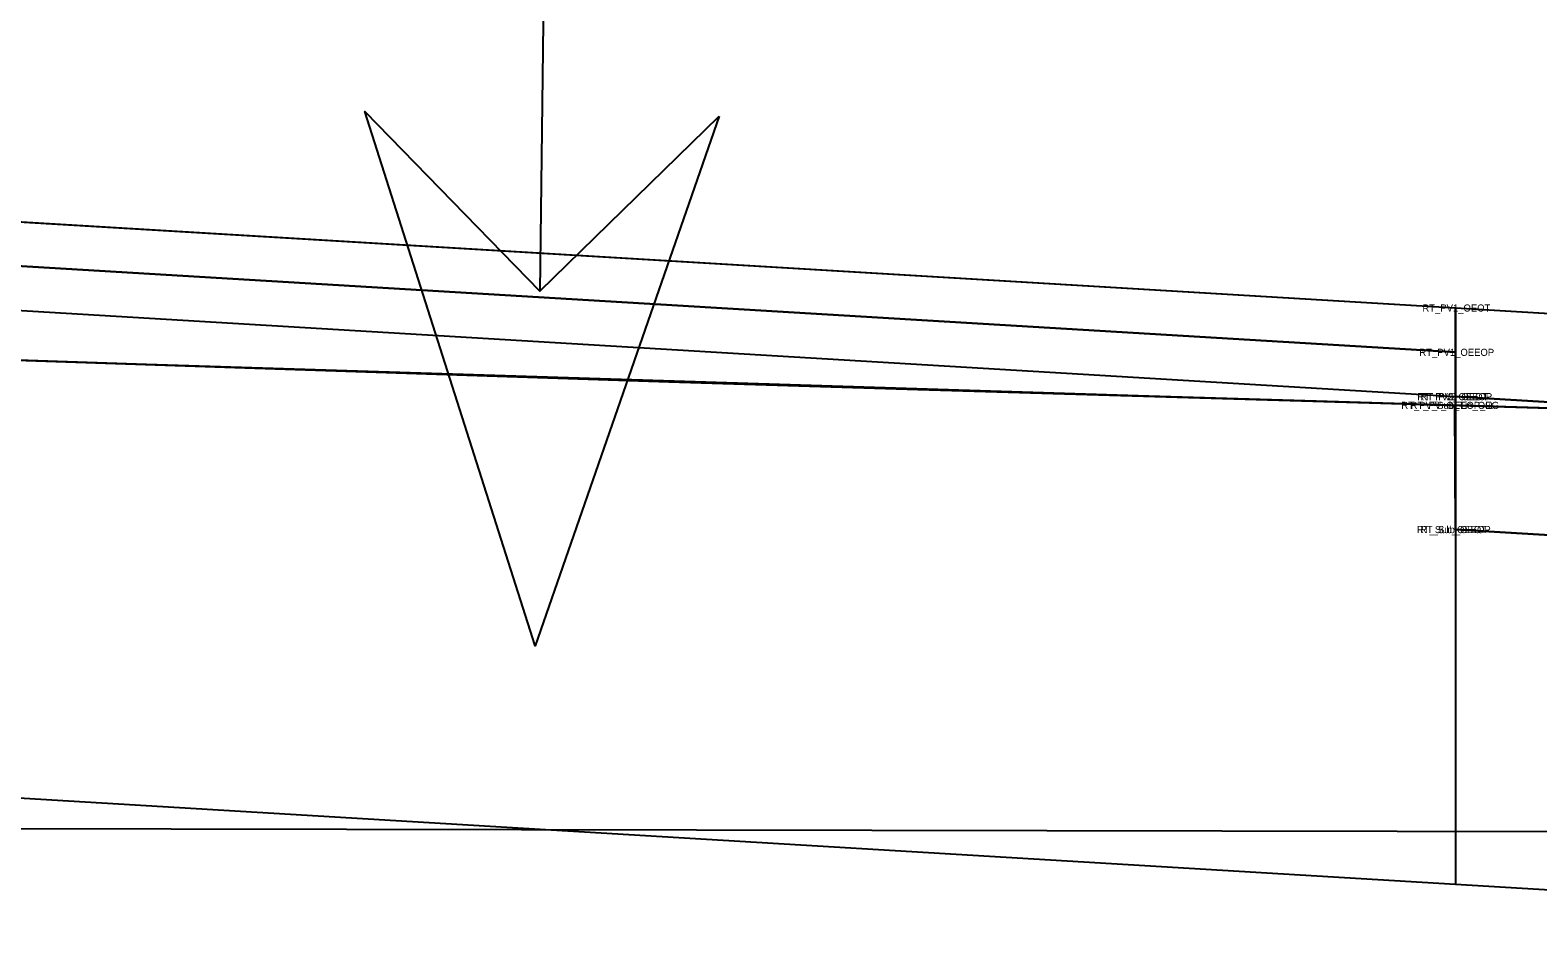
# Model space of a CAD drawing. Extents: x -516 to 303, y -10 to 5017.
# Drawn here: x 157.507 to 161.762, y 3502.323 to 3504.892 of the extents above; entities that cross this region are included whole.
import ezdxf

# ---------------------------------------------------------------- set-up
doc = ezdxf.new("R2010")
doc.units = 0
for name, color, linetype in [('Exist CMT Pavement', 7, 'Continuous'), ('Exist XS Ground Line', 7, 'Continuous'), ('Misc Plan Tools Cell', 7, 'Continuous'), ('Prop CMT Pvmt Course 1', 7, 'Continuous'), ('Prop CMT Pvmt Course 1 Wedge', 7, 'Continuous'), ('Prop CMT Pvmt Course 2', 7, 'Continuous'), ('Prop CMT Pvmt Course 2 Wedge', 7, 'Continuous'), ('Prop CMT Pvmt Course 3', 7, 'Continuous'), ('Prop CMT Pvmt Course 3 Wedge', 7, 'Continuous'), ('Prop CMT Pvmt Surface', 7, 'Continuous'), ('Prop CMT Pvmt Surface Shoulder', 7, 'Continuous'), ('Prop CMT Pvmt Wedge Surface 1', 7, 'Continuous'), ('Prop CMT Pvmt Wedge Surface 2', 7, 'Continuous'), ('Prop CMT Pvmt Wedge Surface 3', 7, 'Continuous'), ('Prop CMT Shld Paved Course 1', 7, 'Continuous'), ('Prop CMT Shld Paved Course 2', 7, 'Continuous'), ('Prop CMT Shld Paved Course 3', 7, 'Continuous'), ('Prop CMT Subgrade Earthwork', 7, 'Continuous'), ('Prop Road Sect_ Material - Bubble + Leader + Bubble Tx', 7, 'Continuous'), ('Prop Road Sect_ Material - Contact (General - Major)', 7, 'Continuous'), ('Prop Road Sect_ Misc - Drafting Aid (solid line)', 7, 'Continuous'), ('Prop Road Sect_ Recs - UC Shallow (Outline)', 7, 'Continuous'), ('Prop Road Sect_ Recs - UC Shallow (Pattern)', 7, 'Continuous'), ('Scratch_Level_0', 7, 'Continuous')]:
    doc.layers.add(name, color=color, linetype=linetype)

msp = doc.modelspace()

# ---------------------------------------------------------------- linework, layer by layer
at = {"layer": 'Exist CMT Pavement'}
msp.add_lwpolyline([(150.0015, 3504.1969), (161.5277, 3503.8336)], dxfattribs=at)
at = {"layer": 'Exist XS Ground Line'}
msp.add_lwpolyline([(125.205, 3503.8945), (131.7518, 3504.2176), (136.6829, 3504.4743), (138.318, 3504.4836), (148.612, 3504.249), (149.068, 3504.2286), (150, 3504.197), (151.3235, 3504.1521), (153.2258, 3504.1006), (154.2229, 3504.0743), (155.6813, 3504.0239), (157.1104, 3503.9729), (158.1124, 3503.9391), (159.3093, 3503.9003), (160.0118, 3503.8781), (163.151, 3503.7853), (163.5861, 3503.7651), (164.5345, 3503.7181), (165.9518, 3503.6102), (166.3074, 3503.5849)], dxfattribs=at)
at = {"layer": 'Misc Plan Tools Cell'}
msp.add_lwpolyline([(159.4515, 3504.6492), (158.9323, 3503.1557), (158.4515, 3504.662), (158.9451, 3504.1557)], close=True, dxfattribs=at)
at = {"layer": 'Prop CMT Pvmt Course 1'}
for points in [[(150, 3504.8), (161.5292, 3504.1082)], [(161.5292, 3503.9832), (150, 3504.675)], [(161.5292, 3504.1082), (161.5292, 3503.8582), (161.5292, 3503.8582), (161.5292, 3503.9832)]]:
    msp.add_lwpolyline(points, dxfattribs=at)
at = {"layer": 'Prop CMT Pvmt Course 1 Wedge'}
msp.add_lwpolyline([(150, 3504.675), (161.5292, 3503.9832)], dxfattribs=at)
at = {"layer": 'Prop CMT Pvmt Course 2'}
msp.add_lwpolyline([(161.5292, 3503.8582), (161.5292, 3503.8582), (161.5292, 3503.8582)], close=True, dxfattribs=at)
msp.add_lwpolyline([(161.5292, 3503.8582), (161.5292, 3503.8582)], dxfattribs=at)
at = {"layer": 'Prop CMT Pvmt Course 2 Wedge'}
msp.add_lwpolyline([(150, 3504.55), (161.5292, 3503.8582)], dxfattribs=at)
at = {"layer": 'Prop CMT Pvmt Course 3'}
for points in [[(161.5292, 3503.8582), (161.5292, 3503.8582), (161.5292, 3503.4832), (161.5292, 3503.4832)], [(161.5292, 3503.4832), (161.5292, 3503.8582)]]:
    msp.add_lwpolyline(points, dxfattribs=at)
at = {"layer": 'Prop CMT Pvmt Course 3 Wedge'}
msp.add_lwpolyline([(150, 3504.55), (161.5292, 3503.8582)], dxfattribs=at)
at = {"layer": 'Prop CMT Pvmt Surface'}
msp.add_line((150, 3504.8), (161.5292, 3504.1082), dxfattribs=at)
at = {"layer": 'Prop CMT Pvmt Surface Shoulder'}
msp.add_line((161.5292, 3504.1082), (163.5292, 3503.9882), dxfattribs=at)
at = {"layer": 'Prop CMT Pvmt Wedge Surface 1'}
for points in [[(150, 3504.675), (161.5292, 3503.9832)], [(161.5292, 3503.8582), (161.5292, 3504.1082)], [(161.5292, 3503.9832), (161.5292, 3503.8582), (161.5292, 3503.8582)]]:
    msp.add_lwpolyline(points, dxfattribs=at)
at = {"layer": 'Prop CMT Pvmt Wedge Surface 2'}
for points in [[(150, 3504.55), (161.5292, 3503.8582)], [(161.5292, 3503.8582), (161.5292, 3504.1082)]]:
    msp.add_lwpolyline(points, dxfattribs=at)
at = {"layer": 'Prop CMT Pvmt Wedge Surface 3'}
for points in [[(150, 3504.55), (161.5292, 3503.8582)], [(161.5292, 3503.8582), (161.5292, 3504.1082)]]:
    msp.add_lwpolyline(points, dxfattribs=at)
at = {"layer": 'Prop CMT Shld Paved Course 1'}
for points in [[(161.5292, 3504.1082), (163.5292, 3503.9882), (163.7952, 3503.7223)], [(161.5292, 3503.8582), (161.5292, 3504.1082)], [(163.7952, 3503.7223), (161.5292, 3503.8582)]]:
    msp.add_lwpolyline(points, dxfattribs=at)
at = {"layer": 'Prop CMT Shld Paved Course 2'}
for points in [[(161.5292, 3503.8582), (163.7952, 3503.7223)], [(163.7952, 3503.7223), (161.5292, 3503.8582)], [(161.5292, 3503.8582), (161.5292, 3503.8582)]]:
    msp.add_lwpolyline(points, dxfattribs=at)
at = {"layer": 'Prop CMT Shld Paved Course 3'}
for points in [[(161.5292, 3503.8582), (163.7952, 3503.7223)], [(161.5292, 3503.4832), (161.5292, 3503.8582)], [(164.1941, 3503.3234), (161.5292, 3503.4832)]]:
    msp.add_lwpolyline(points, dxfattribs=at)
at = {"layer": 'Prop CMT Subgrade Earthwork'}
for q in [(161.5277, 3503.8336), (164.1941, 3503.3234), (161.5292, 3503.4832)]:
    msp.add_line((161.5292, 3503.4832), q, dxfattribs=at)
at = {"layer": 'Prop Road Sect_ Material - Bubble + Leader + Bubble Tx'}
msp.add_line((158.9796, 3506.8602), (158.9451, 3504.1557), dxfattribs=at)
at = {"layer": 'Prop Road Sect_ Material - Contact (General - Major)'}
msp.add_line((176.8467, 3502.6017), (116.479, 3502.7189), dxfattribs=at)
at = {"layer": 'Prop Road Sect_ Misc - Drafting Aid (solid line)'}
msp.add_line((161.5292, 3503.4832), (161.5292, 3502.4832), dxfattribs=at)
at = {"layer": 'Prop Road Sect_ Recs - UC Shallow (Outline)'}
msp.add_lwpolyline([(165.1941, 3503.3234), (165.1941, 3503.6679), (164.5345, 3503.7181), (163.5861, 3503.7651), (163.151, 3503.7853), (159.3093, 3503.9003), (158.1124, 3503.9391), (157.1104, 3503.9729), (155.6813, 3504.0239), (154.2229, 3504.0743), (151.3235, 3504.1521), (150, 3504.197), (149.068, 3504.2286), (148.612, 3504.249), (148.0014, 3504.2629), (145.4104, 3504.322), (145.4104, 3503.4504), (148, 3503.295), (161.5292, 3502.4832), (164.1941, 3502.3234), (165.1941, 3502.3234), (165.1941, 3503.3234)], dxfattribs=at)
at = {"layer": 'Prop Road Sect_ Recs - UC Shallow (Pattern)'}
msp.add_lwpolyline([(165.1941, 3503.3234), (165.1941, 3503.6679), (164.5345, 3503.7181), (163.5861, 3503.7651), (163.151, 3503.7853), (159.3093, 3503.9003), (158.1124, 3503.9391), (157.1104, 3503.9729), (155.6813, 3504.0239), (154.2229, 3504.0743), (151.3235, 3504.1521), (150, 3504.197), (149.068, 3504.2286), (148.612, 3504.249), (148.0014, 3504.2629), (145.4104, 3504.322), (145.4104, 3503.4504), (148, 3503.295), (161.5292, 3502.4832), (164.1941, 3502.3234), (165.1941, 3502.3234), (165.1941, 3503.3234)], dxfattribs=at)

# ---------------------------------------------------------------- texts
at = {"layer": 'Scratch_Level_0'}
for s, p in [('RT_PV1_OEOT', (161.4361, 3504.0982)), ('RT_PV1_OEEOP', (161.4275, 3503.9732)), ('RT_PV2_OEEOP', (161.4218, 3503.8482)), ('RT_PV3_OEEOP', (161.4218, 3503.8482)), ('RT_PV3_OEOT', (161.4305, 3503.8482)), ('RT_PV2_OEOT', (161.4305, 3503.8482)), ('RT_PV_Sub_Tie_Out', (161.3767, 3503.8236)), ('RT_PV_OEEOP_EG', (161.4027, 3503.8236)), ('RT_Sub_OEEOP', (161.4208, 3503.4732)), ('RT_Sub_OEOT', (161.4295, 3503.4732))]:
    msp.add_text(s, height=0.02, dxfattribs=at).set_placement(p)

doc.saveas('drawing.dxf')
